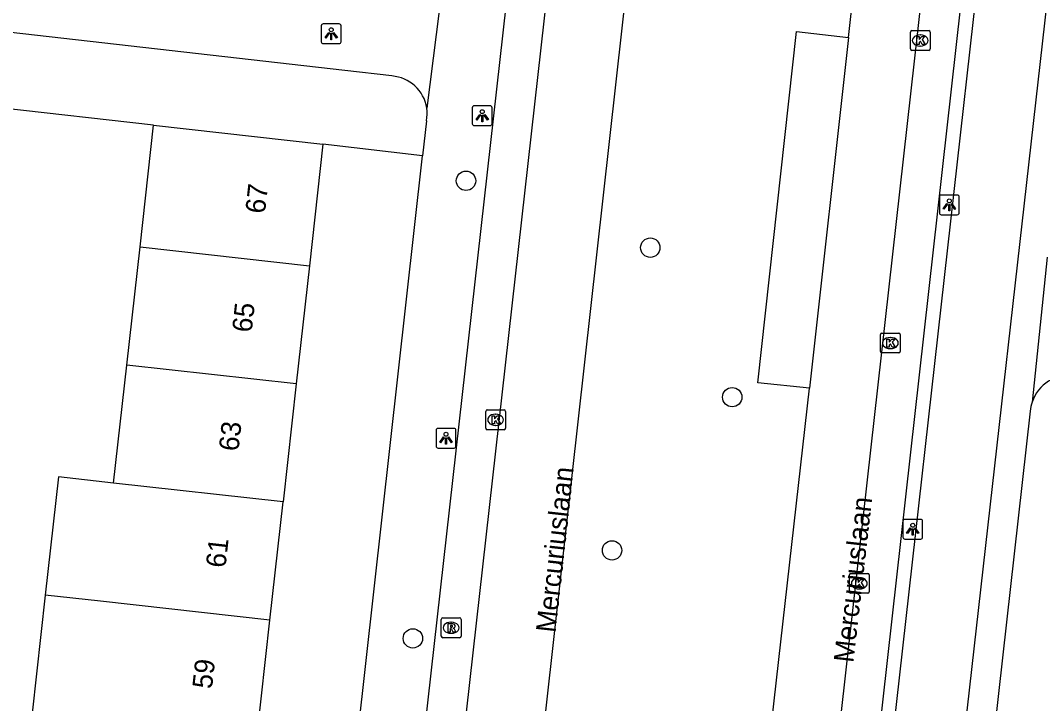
# Model space of a CAD drawing. Extents: x 161928 to 163055, y 386475 to 387428.
# Drawn here: x 162259.5 to 162311.1, y 386877.6 to 386912.1 of the extents above; entities that cross this region are included whole.
import ezdxf

# ---------------------------------------------------------------- set-up
doc = ezdxf.new("R2010")
doc.units = 0
for name, color, linetype in [('IMGEO_Boom', 7, 'Continuous'), ('IMGEO_Fietspad_gesloten', 7, 'Continuous'), ('IMGEO_Grasland_overig', 7, 'Continuous'), ('IMGEO_Kolk', 7, 'Continuous'), ('IMGEO_Lichtpunt', 7, 'Continuous'), ('IMGEO_Openbare_ruimte_label', 7, 'Continuous'), ('IMGEO_Pand', 7, 'Continuous'), ('IMGEO_Pand_nummerreeks', 7, 'Continuous'), ('IMGEO_Parkeervlak_open', 7, 'Continuous'), ('IMGEO_Rijbaan_lokaal_open', 7, 'Continuous'), ('IMGEO_Rioolput', 7, 'Continuous'), ('IMGEO_Voetpad_open', 7, 'Continuous')]:
    doc.layers.add(name, color=color, linetype=linetype)

msp = doc.modelspace()

# ---------------------------------------------------------------- linework, layer by layer
at = {"layer": 'IMGEO_Boom'}
for centre in [(162282.028, 386903.967), (162291.334, 386900.591), (162295.471, 386893.041), (162289.402, 386885.304), (162279.345, 386880.858)]:
    msp.add_circle(centre, 0.489, dxfattribs=at)
at = {"layer": 'IMGEO_Fietspad_gesloten'}
for points in [[(162317.167, 386964.756), (162315.626, 386950.841), (162303.065, 386839.488)], [(162299.883, 386842.935), (162312.507, 386955.255), (162313.199, 386961.491)]]:
    msp.add_lwpolyline(points, dxfattribs=at)
at = {"layer": 'IMGEO_Grasland_overig'}
for points in [[(162266.253, 386906.774), (162258.473, 386907.653)], [(162279.836, 386905.223), (162274.804, 386905.82)]]:
    msp.add_lwpolyline(points, dxfattribs=at)
at = {"layer": 'IMGEO_Kolk'}
for p, q in [((162304.466, 386910.627), (162304.466, 386911.479)), ((162304.541, 386911.553), (162305.393, 386911.553)), ((162304.954, 386911.333), (162304.979, 386911.333)), ((162305.467, 386911.479), (162305.467, 386910.627)), ((162304.977, 386910.773), (162304.952, 386910.773)), ((162305.393, 386910.553), (162304.541, 386910.553)), ((162303.032, 386896.274), (162303.884, 386896.274)), ((162302.957, 386895.348), (162302.957, 386896.2)), ((162303.445, 386896.054), (162303.47, 386896.054)), ((162303.958, 386896.2), (162303.958, 386895.348)), ((162303.884, 386895.274), (162303.032, 386895.274)), ((162303.468, 386895.494), (162303.443, 386895.494)), ((162283.024, 386891.472), (162283.024, 386892.324)), ((162283.099, 386892.398), (162283.951, 386892.398)), ((162283.512, 386892.178), (162283.537, 386892.178)), ((162284.025, 386892.324), (162284.025, 386891.472)), ((162283.535, 386891.618), (162283.51, 386891.618)), ((162283.951, 386891.398), (162283.099, 386891.398)), ((162301.389, 386883.209), (162301.389, 386884.061)), ((162301.464, 386884.135), (162302.316, 386884.135)), ((162301.877, 386883.915), (162301.902, 386883.915)), ((162302.39, 386884.061), (162302.39, 386883.209)), ((162301.9, 386883.355), (162301.875, 386883.355)), ((162302.316, 386883.135), (162301.464, 386883.135))]:
    msp.add_line(p, q, dxfattribs=at)
for points in [[(162304.466, 386910.627), (162304.466, 386911.479)], [(162304.541, 386911.553), (162305.393, 386911.553)], [(162304.787, 386911.253), (162304.91, 386911.253), (162304.91, 386911.102), (162305.04, 386911.253), (162305.204, 386911.253), (162305.058, 386911.102), (162305.211, 386910.853), (162305.059, 386910.853), (162304.974, 386911.017), (162304.91, 386910.95), (162304.91, 386910.853), (162304.787, 386910.853), (162304.787, 386911.253)], [(162305.467, 386911.479), (162305.467, 386910.627)], [(162305.393, 386910.553), (162304.541, 386910.553)], [(162303.032, 386896.274), (162303.884, 386896.274)], [(162302.957, 386895.348), (162302.957, 386896.2)], [(162303.278, 386895.974), (162303.401, 386895.974), (162303.401, 386895.823), (162303.531, 386895.974), (162303.695, 386895.974), (162303.549, 386895.823), (162303.702, 386895.574), (162303.55, 386895.574), (162303.465, 386895.738), (162303.401, 386895.671), (162303.401, 386895.574), (162303.278, 386895.574), (162303.278, 386895.974)], [(162303.958, 386896.2), (162303.958, 386895.348)], [(162303.884, 386895.274), (162303.032, 386895.274)], [(162283.024, 386891.472), (162283.024, 386892.324)], [(162283.099, 386892.398), (162283.951, 386892.398)], [(162284.025, 386892.324), (162284.025, 386891.472)], [(162283.345, 386892.098), (162283.468, 386892.098), (162283.468, 386891.947), (162283.598, 386892.098), (162283.762, 386892.098), (162283.616, 386891.947), (162283.769, 386891.698), (162283.617, 386891.698), (162283.532, 386891.862), (162283.468, 386891.795), (162283.468, 386891.698), (162283.345, 386891.698), (162283.345, 386892.098)], [(162283.951, 386891.398), (162283.099, 386891.398)], [(162301.389, 386883.209), (162301.389, 386884.061)], [(162301.464, 386884.135), (162302.316, 386884.135)], [(162302.39, 386884.061), (162302.39, 386883.209)], [(162301.71, 386883.835), (162301.833, 386883.835), (162301.833, 386883.684), (162301.963, 386883.835), (162302.127, 386883.835), (162301.981, 386883.684), (162302.134, 386883.435), (162301.982, 386883.435), (162301.897, 386883.599), (162301.833, 386883.532), (162301.833, 386883.435), (162301.71, 386883.435), (162301.71, 386883.835)], [(162302.316, 386883.135), (162301.464, 386883.135)]]:
    msp.add_lwpolyline(points, dxfattribs=at)
for centre, start, end in [((162304.543, 386911.477), 91.552, 178.448), ((162304.543, 386911.477), 91.552, 178.448), ((162305.391, 386911.477), 1.552, 88.448), ((162305.391, 386911.477), 1.552, 88.448), ((162304.543, 386910.629), 181.552, 268.448), ((162304.543, 386910.629), 181.552, 268.448), ((162305.391, 386910.629), 271.552, 358.448), ((162305.391, 386910.629), 271.552, 358.448), ((162303.034, 386896.198), 91.552, 178.448), ((162303.034, 386896.198), 91.552, 178.448), ((162303.882, 386896.198), 1.552, 88.448), ((162303.882, 386896.198), 1.552, 88.448), ((162303.034, 386895.35), 181.552, 268.448), ((162303.034, 386895.35), 181.552, 268.448), ((162303.882, 386895.35), 271.552, 358.448), ((162303.882, 386895.35), 271.552, 358.448), ((162283.101, 386892.322), 91.552, 178.448), ((162283.101, 386892.322), 91.552, 178.448), ((162283.949, 386892.322), 1.552, 88.448), ((162283.949, 386892.322), 1.552, 88.448), ((162283.101, 386891.474), 181.552, 268.448), ((162283.101, 386891.474), 181.552, 268.448), ((162283.949, 386891.474), 271.552, 358.448), ((162283.949, 386891.474), 271.552, 358.448), ((162301.466, 386884.059), 91.552, 178.448), ((162301.466, 386884.059), 91.552, 178.448), ((162302.314, 386884.059), 1.552, 88.448), ((162302.314, 386884.059), 1.552, 88.448), ((162301.466, 386883.211), 181.552, 268.448), ((162301.466, 386883.211), 181.552, 268.448), ((162302.314, 386883.211), 271.552, 358.448), ((162302.314, 386883.211), 271.552, 358.448)]:
    msp.add_arc(centre, 0.0765, start, end, dxfattribs=at)
for centre, major_axis, ratio, start_param, end_param in [((162304.953, 386911.053), (-0.387, 0.002), 0.722429, 4.712389, 7.853982), ((162304.978, 386911.053), (-0.39, 0.002), 0.717154, 1.570796, 4.712389), ((162303.444, 386895.774), (-0.387, 0.002), 0.722429, 4.712389, 7.853982), ((162303.469, 386895.774), (-0.39, 0.002), 0.717154, 1.570796, 4.712389), ((162283.511, 386891.898), (-0.387, 0.002), 0.722429, 4.712389, 7.853982), ((162283.536, 386891.898), (-0.39, 0.002), 0.717154, 1.570796, 4.712389), ((162301.876, 386883.635), (-0.387, 0.002), 0.722429, 4.712389, 7.853982), ((162301.901, 386883.635), (-0.39, 0.002), 0.717154, 1.570796, 4.712389)]:
    msp.add_ellipse(centre, major_axis=major_axis, ratio=ratio, start_param=start_param, end_param=end_param, dxfattribs=at)
at = {"layer": 'IMGEO_Lichtpunt'}
for p, q in [((162274.722, 386911.799), (162274.722, 386910.992)), ((162274.722, 386911.799), (162274.722, 386910.992)), ((162275.624, 386911.894), (162274.816, 386911.894)), ((162275.624, 386911.894), (162274.816, 386911.894)), ((162275.718, 386910.992), (162275.718, 386911.799)), ((162275.718, 386910.992), (162275.718, 386911.799)), ((162274.816, 386910.898), (162275.624, 386910.898)), ((162274.816, 386910.898), (162275.624, 386910.898)), ((162282.347, 386907.66), (162282.347, 386906.853)), ((162282.347, 386907.66), (162282.347, 386906.853)), ((162283.249, 386907.755), (162282.441, 386907.755)), ((162283.249, 386907.755), (162282.441, 386907.755)), ((162283.343, 386906.853), (162283.343, 386907.66)), ((162283.343, 386906.853), (162283.343, 386907.66)), ((162282.441, 386906.759), (162283.249, 386906.759)), ((162282.441, 386906.759), (162283.249, 386906.759)), ((162305.935, 386903.153), (162305.935, 386902.346)), ((162305.935, 386903.153), (162305.935, 386902.346)), ((162306.837, 386903.248), (162306.029, 386903.248)), ((162306.837, 386903.248), (162306.029, 386903.248)), ((162306.931, 386902.346), (162306.931, 386903.153)), ((162306.931, 386902.346), (162306.931, 386903.153)), ((162306.029, 386902.252), (162306.837, 386902.252)), ((162306.029, 386902.252), (162306.837, 386902.252)), ((162280.521, 386891.369), (162280.521, 386890.562)), ((162280.521, 386891.369), (162280.521, 386890.562)), ((162281.423, 386891.464), (162280.615, 386891.464)), ((162281.423, 386891.464), (162280.615, 386891.464)), ((162281.517, 386890.562), (162281.517, 386891.369)), ((162281.517, 386890.562), (162281.517, 386891.369)), ((162280.615, 386890.468), (162281.423, 386890.468)), ((162280.615, 386890.468), (162281.423, 386890.468)), ((162304.09, 386886.775), (162304.09, 386885.968)), ((162304.09, 386886.775), (162304.09, 386885.968)), ((162304.992, 386886.87), (162304.184, 386886.87)), ((162304.992, 386886.87), (162304.184, 386886.87)), ((162305.086, 386885.968), (162305.086, 386886.775)), ((162305.086, 386885.968), (162305.086, 386886.775)), ((162304.184, 386885.874), (162304.992, 386885.874)), ((162304.184, 386885.874), (162304.992, 386885.874))]:
    msp.add_line(p, q, dxfattribs=at)
for points in [[(162275.096, 386911.463), (162275.135, 386911.435), (162274.947, 386911.173), (162274.909, 386911.2), (162275.096, 386911.463)], [(162275.198, 386911.415), (162275.245, 386911.415), (162275.245, 386911.093), (162275.198, 386911.093), (162275.198, 386911.415)], [(162275.308, 386911.435), (162275.346, 386911.462), (162275.533, 386911.2), (162275.494, 386911.172), (162275.308, 386911.435)], [(162282.721, 386907.324), (162282.76, 386907.296), (162282.572, 386907.034), (162282.534, 386907.061), (162282.721, 386907.324)], [(162282.823, 386907.276), (162282.87, 386907.276), (162282.87, 386906.954), (162282.823, 386906.954), (162282.823, 386907.276)], [(162282.933, 386907.296), (162282.971, 386907.323), (162283.158, 386907.061), (162283.119, 386907.033), (162282.933, 386907.296)], [(162306.309, 386902.817), (162306.348, 386902.789), (162306.16, 386902.527), (162306.122, 386902.554), (162306.309, 386902.817)], [(162306.411, 386902.769), (162306.458, 386902.769), (162306.458, 386902.447), (162306.411, 386902.447), (162306.411, 386902.769)], [(162306.521, 386902.789), (162306.559, 386902.816), (162306.746, 386902.554), (162306.707, 386902.526), (162306.521, 386902.789)], [(162280.895, 386891.033), (162280.934, 386891.005), (162280.746, 386890.743), (162280.708, 386890.77), (162280.895, 386891.033)], [(162280.997, 386890.985), (162281.044, 386890.985), (162281.044, 386890.663), (162280.997, 386890.663), (162280.997, 386890.985)], [(162281.107, 386891.005), (162281.145, 386891.032), (162281.332, 386890.77), (162281.293, 386890.742), (162281.107, 386891.005)], [(162304.464, 386886.439), (162304.503, 386886.411), (162304.315, 386886.149), (162304.277, 386886.176), (162304.464, 386886.439)], [(162304.676, 386886.411), (162304.714, 386886.438), (162304.901, 386886.176), (162304.862, 386886.148), (162304.676, 386886.411)], [(162304.566, 386886.391), (162304.613, 386886.391), (162304.613, 386886.069), (162304.566, 386886.069), (162304.566, 386886.391)]]:
    msp.add_lwpolyline(points, dxfattribs=at)
for centre in [(162275.221, 386911.597), (162282.846, 386907.458), (162306.434, 386902.951), (162281.02, 386891.167), (162304.589, 386886.573)]:
    msp.add_circle(centre, 0.0994, dxfattribs=at)
for centre, start, end in [((162274.816, 386911.799), 90, 180), ((162274.816, 386911.799), 90, 180), ((162275.624, 386911.799), 0, 90), ((162275.624, 386911.799), 0, 90), ((162274.816, 386910.992), 180, 270), ((162274.816, 386910.992), 180, 270), ((162275.624, 386910.992), 270, 0), ((162275.624, 386910.992), 270, 360), ((162282.441, 386907.66), 90, 180), ((162282.441, 386907.66), 90, 180), ((162283.249, 386907.66), 0, 90), ((162283.249, 386907.66), 0, 90), ((162282.441, 386906.853), 180, 270), ((162282.441, 386906.853), 180, 270), ((162283.249, 386906.853), 270, 0), ((162283.249, 386906.853), 270, 360), ((162306.029, 386903.153), 90, 180), ((162306.029, 386903.153), 90, 180), ((162306.837, 386903.153), 0, 90), ((162306.837, 386903.153), 0, 90), ((162306.029, 386902.346), 180, 270), ((162306.029, 386902.346), 180, 270), ((162306.837, 386902.346), 270, 0), ((162306.837, 386902.346), 270, 360), ((162280.615, 386891.369), 90, 180), ((162280.615, 386891.369), 90, 180), ((162281.423, 386891.369), 0, 90), ((162281.423, 386891.369), 0, 90), ((162280.615, 386890.562), 180, 270), ((162280.615, 386890.562), 180, 270), ((162281.423, 386890.562), 270, 0), ((162281.423, 386890.562), 270, 360), ((162304.184, 386886.775), 90, 180), ((162304.184, 386886.775), 90, 180), ((162304.992, 386886.775), 0, 90), ((162304.992, 386886.775), 0, 90), ((162304.184, 386885.968), 180, 270), ((162304.184, 386885.968), 180, 270), ((162304.992, 386885.968), 270, 0), ((162304.992, 386885.968), 270, 360)]:
    msp.add_arc(centre, 0.0946, start, end, dxfattribs=at)
at = {"layer": 'IMGEO_Pand'}
for points in [[(162265.567, 386900.628), (162266.253, 386906.774)], [(162266.253, 386906.774), (162274.804, 386905.82)], [(162274.804, 386905.82), (162274.118, 386899.673)], [(162264.902, 386894.665), (162265.567, 386900.628)], [(162265.567, 386900.628), (162274.118, 386899.673)], [(162274.118, 386899.673), (162273.453, 386893.71)], [(162264.237, 386888.702), (162264.902, 386894.665)], [(162273.453, 386893.71), (162264.902, 386894.665)], [(162273.453, 386893.71), (162272.788, 386887.747)], [(162264.237, 386888.702), (162261.45, 386889.013), (162260.785, 386883.05)], [(162272.788, 386887.747), (162264.237, 386888.702)], [(162272.123, 386881.784), (162272.788, 386887.747)], [(162260.785, 386883.05), (162260.12, 386877.088), (162262.907, 386876.777)], [(162272.123, 386881.784), (162263.572, 386882.739), (162260.785, 386883.05)], [(162271.458, 386875.822), (162272.123, 386881.784)]]:
    msp.add_lwpolyline(points, dxfattribs=at)
at = {"layer": 'IMGEO_Parkeervlak_open'}
for points in [[(162312.076, 386958.208), (162299.828, 386848.786)], [(162299.377, 386893.49), (162296.758, 386893.764), (162298.724, 386911.513), (162301.337, 386911.211)]]:
    msp.add_lwpolyline(points, dxfattribs=at)
at = {"layer": 'IMGEO_Rijbaan_lokaal_open'}
for points in [[(162297.693, 386847.773), (162310.198, 386959.221)], [(162301.337, 386911.211), (162306.752, 386959.631)], [(162301.337, 386911.211), (162299.377, 386893.49)], [(162293.554, 386841.928), (162293.809, 386844.193), (162299.377, 386893.49)]]:
    msp.add_lwpolyline(points, dxfattribs=at)
at = {"layer": 'IMGEO_Rioolput'}
for p, q in [((162280.78, 386880.968), (162280.78, 386881.82)), ((162280.855, 386881.894), (162281.707, 386881.894)), ((162281.781, 386881.82), (162281.781, 386880.968)), ((162281.268, 386881.674), (162281.293, 386881.674)), ((162281.707, 386880.894), (162280.855, 386880.894)), ((162281.291, 386881.114), (162281.266, 386881.114))]:
    msp.add_line(p, q, dxfattribs=at)
for points in [[(162280.78, 386880.968), (162280.78, 386881.82)], [(162280.855, 386881.894), (162281.707, 386881.894)], [(162281.781, 386881.82), (162281.781, 386880.968)], [(162281.369, 386881.592), (162281.117, 386881.594), (162281.117, 386881.194)], [(162281.117, 386881.194), (162281.241, 386881.194), (162281.241, 386881.356), (162281.252, 386881.356)], [(162281.295, 386881.513), (162281.241, 386881.513), (162281.241, 386881.432)], [(162281.241, 386881.432), (162281.293, 386881.432)], [(162281.299, 386881.327), (162281.37, 386881.194), (162281.51, 386881.194), (162281.445, 386881.32)], [(162281.707, 386880.894), (162280.855, 386880.894)]]:
    msp.add_lwpolyline(points, dxfattribs=at)
for centre, radius, start, end in [((162280.857, 386881.818), 0.0765, 91.552, 178.448), ((162280.857, 386881.818), 0.0765, 91.552, 178.448), ((162281.705, 386881.818), 0.0765, 1.552, 88.448), ((162281.705, 386881.818), 0.0765, 1.552, 88.448), ((162281.251, 386881.303), 0.0533, 26.0293, 88.6989), ((162281.277, 386881.621), 0.19, 274.7715, 282.9687), ((162281.301, 386881.417), 0.0964, 77.0061, 93.1865), ((162281.315, 386881.474), 0.0378, 276.6634, 79.6772), ((162281.368, 386881.482), 0.109, 350.3612, 89.416), ((162281.366, 386881.482), 0.112, 277.5842, 350.9817), ((162281.35, 386881.267), 0.108, 29.5134, 73.7905), ((162280.857, 386880.97), 0.0765, 181.552, 268.448), ((162280.857, 386880.97), 0.0765, 181.552, 268.448), ((162281.705, 386880.97), 0.0765, 271.552, 358.448), ((162281.705, 386880.97), 0.0765, 271.552, 358.448)]:
    msp.add_arc(centre, radius, start, end, dxfattribs=at)
for centre, major_axis, ratio, start_param, end_param in [((162281.267, 386881.394), (-0.387, 0.002), 0.722429, 4.712389, 7.853982), ((162281.292, 386881.394), (-0.39, 0.002), 0.717154, 1.570796, 4.712389)]:
    msp.add_ellipse(centre, major_axis=major_axis, ratio=ratio, start_param=start_param, end_param=end_param, dxfattribs=at)
at = {"layer": 'IMGEO_Voetpad_open'}
for points in [[(162293.056, 386940.001), (162285.144, 386869.204)], [(162278.952, 386849.57), (162286.473, 386916.537)], [(162284.366, 386915.643), (162277.087, 386850.951)], [(162280.834, 386913.899), (162280.046, 386907.644)], [(162278.287, 386909.261), (162275.913, 386909.538), (162256.227, 386911.782)], [(162280.035, 386907.002), (162279.836, 386905.223)], [(162272.9, 386843.099), (162279.836, 386905.223)], [(162311.382, 386900.118), (162310.614, 386892.796)], [(162310.516, 386892.338), (162308.514, 386874.479)]]:
    msp.add_lwpolyline(points, dxfattribs=at)
for centre, radius, start, end in [((162278.156, 386907.353), 1.912, 8.7418, 86.0753), ((162278.11, 386907.356), 1.957, 349.5764, 8.4604), ((162312.488, 386892.158), 1.98, 82.3364, 161.201), ((162312.431, 386892.168), 1.922, 160.925, 174.9197)]:
    msp.add_arc(centre, radius, start, end, dxfattribs=at)

# ---------------------------------------------------------------- texts
at = {"layer": 'IMGEO_Openbare_ruimte_label'}
for rotation, p in [(83.6851, (162286.548, 386881.118)), (83.4574, (162301.586, 386879.603))]:
    msp.add_text('Mercuriuslaan', height=1, rotation=rotation, dxfattribs=at).set_placement(p)
at = {"layer": 'IMGEO_Pand_nummerreeks'}
for s, rotation, p in [('67', 83.6353, (162271.873, 386902.279)), ('65', 83.6353, (162271.204, 386896.279)), ('63', 83.6353, (162270.535, 386890.28)), ('61', 83.6346, (162269.879, 386884.392)), ('59', 83.6346, (162269.197, 386878.28))]:
    msp.add_text(s, height=1, rotation=rotation, dxfattribs=at).set_placement(p)

doc.saveas('drawing.dxf')
